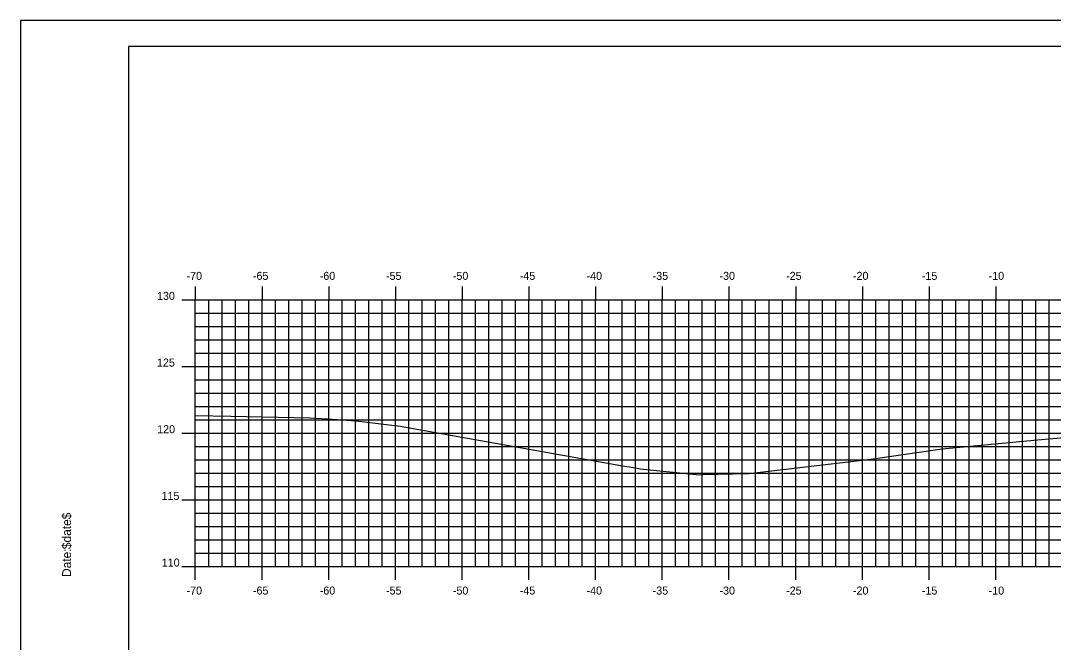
# Model space of a CAD drawing. Extents: x 852847 to 853019, y 365624 to 365734.
# Drawn here: x 852847.2 to 852924.6, y 365687.3 to 365734 of the extents above; entities that cross this region are included whole.
import ezdxf

# ---------------------------------------------------------------- set-up
doc = ezdxf.new("R2010")
doc.units = 0
for name, color, linetype in [('BORDER', 7, 'Continuous'), ('H_V ANNOTATION', 7, 'Continuous'), ('MAJOR', 7, 'Continuous'), ('MINOR', 7, 'Continuous'), ('PLOT BOUNDARY', 7, 'Continuous'), ('S_Roadway_Centerline', 7, 'Continuous')]:
    doc.layers.add(name, color=color, linetype=linetype)

msp = doc.modelspace()

# ---------------------------------------------------------------- linework, layer by layer
at = {"layer": 'BORDER'}
msp.add_lwpolyline([(852855.305, 365627.027), (853015.305, 365627.027), (853015.305, 365732.027), (852855.305, 365732.027)], close=True, dxfattribs=at)
at = {"layer": 'MAJOR'}
for p, q in [((852860.305, 365714.029), (852860.305, 365713.027)), ((852865.305, 365714.029), (852865.305, 365713.027)), ((852870.305, 365714.029), (852870.305, 365713.027)), ((852875.305, 365714.029), (852875.305, 365713.027)), ((852880.305, 365714.029), (852880.305, 365713.027)), ((852885.305, 365714.029), (852885.305, 365713.027)), ((852890.305, 365714.029), (852890.305, 365713.027)), ((852895.305, 365714.029), (852895.305, 365713.027)), ((852900.305, 365714.029), (852900.305, 365713.027)), ((852905.305, 365714.029), (852905.305, 365713.027)), ((852910.305, 365714.029), (852910.305, 365713.027)), ((852915.305, 365714.029), (852915.305, 365713.027)), ((852920.305, 365714.029), (852920.305, 365713.027)), ((852859.303, 365713.027), (852860.305, 365713.027)), ((852860.305, 365713.027), (853000.305, 365713.027)), ((852860.305, 365693.027), (852860.305, 365713.027)), ((852860.305, 365693.027), (852860.305, 365713.027)), ((852860.305, 365713.027), (853000.305, 365713.027)), ((852865.305, 365693.027), (852865.305, 365713.027)), ((852870.305, 365693.027), (852870.305, 365713.027)), ((852875.305, 365693.027), (852875.305, 365713.027)), ((852880.305, 365693.027), (852880.305, 365713.027)), ((852885.305, 365693.027), (852885.305, 365713.027)), ((852890.305, 365693.027), (852890.305, 365713.027)), ((852895.305, 365693.027), (852895.305, 365713.027)), ((852900.305, 365693.027), (852900.305, 365713.027)), ((852905.305, 365693.027), (852905.305, 365713.027)), ((852910.305, 365693.027), (852910.305, 365713.027)), ((852915.305, 365693.027), (852915.305, 365713.027)), ((852920.305, 365693.027), (852920.305, 365713.027)), ((852859.303, 365708.027), (852860.305, 365708.027)), ((852860.305, 365708.027), (853000.305, 365708.027)), ((852859.303, 365703.027), (852860.305, 365703.027)), ((852860.305, 365703.027), (853000.305, 365703.027)), ((852859.303, 365698.027), (852860.305, 365698.027)), ((852860.305, 365698.027), (853000.305, 365698.027)), ((852859.303, 365693.027), (852860.305, 365693.027)), ((852860.305, 365693.027), (853000.305, 365693.027)), ((852860.305, 365693.027), (853000.305, 365693.027)), ((852860.305, 365692.025), (852860.305, 365693.027)), ((852865.305, 365692.025), (852865.305, 365693.027)), ((852870.305, 365692.025), (852870.305, 365693.027)), ((852875.305, 365692.025), (852875.305, 365693.027)), ((852880.305, 365692.025), (852880.305, 365693.027)), ((852885.305, 365692.025), (852885.305, 365693.027)), ((852890.305, 365692.025), (852890.305, 365693.027)), ((852895.305, 365692.025), (852895.305, 365693.027)), ((852900.305, 365692.025), (852900.305, 365693.027)), ((852905.305, 365692.025), (852905.305, 365693.027)), ((852910.305, 365692.025), (852910.305, 365693.027)), ((852915.305, 365692.025), (852915.305, 365693.027)), ((852920.305, 365692.025), (852920.305, 365693.027))]:
    msp.add_line(p, q, dxfattribs=at)
at = {"layer": 'MINOR'}
for p, q in [((852861.305, 365693.027), (852861.305, 365713.027)), ((852862.305, 365693.027), (852862.305, 365713.027)), ((852863.305, 365693.027), (852863.305, 365713.027)), ((852864.305, 365693.027), (852864.305, 365713.027)), ((852866.305, 365693.027), (852866.305, 365713.027)), ((852867.305, 365693.027), (852867.305, 365713.027)), ((852868.305, 365693.027), (852868.305, 365713.027)), ((852869.305, 365693.027), (852869.305, 365713.027)), ((852871.305, 365693.027), (852871.305, 365713.027)), ((852872.305, 365693.027), (852872.305, 365713.027)), ((852873.305, 365693.027), (852873.305, 365713.027)), ((852874.305, 365693.027), (852874.305, 365713.027)), ((852876.305, 365693.027), (852876.305, 365713.027)), ((852877.305, 365693.027), (852877.305, 365713.027)), ((852878.305, 365693.027), (852878.305, 365713.027)), ((852879.305, 365693.027), (852879.305, 365713.027)), ((852881.305, 365693.027), (852881.305, 365713.027)), ((852882.305, 365693.027), (852882.305, 365713.027)), ((852883.305, 365693.027), (852883.305, 365713.027)), ((852884.305, 365693.027), (852884.305, 365713.027)), ((852886.305, 365693.027), (852886.305, 365713.027)), ((852887.305, 365693.027), (852887.305, 365713.027)), ((852888.305, 365693.027), (852888.305, 365713.027)), ((852889.305, 365693.027), (852889.305, 365713.027)), ((852891.305, 365693.027), (852891.305, 365713.027)), ((852892.305, 365693.027), (852892.305, 365713.027)), ((852893.305, 365693.027), (852893.305, 365713.027)), ((852894.305, 365693.027), (852894.305, 365713.027)), ((852896.305, 365693.027), (852896.305, 365713.027)), ((852897.305, 365693.027), (852897.305, 365713.027)), ((852898.305, 365693.027), (852898.305, 365713.027)), ((852899.305, 365693.027), (852899.305, 365713.027)), ((852901.305, 365693.027), (852901.305, 365713.027)), ((852902.305, 365693.027), (852902.305, 365713.027)), ((852903.305, 365693.027), (852903.305, 365713.027)), ((852904.305, 365693.027), (852904.305, 365713.027)), ((852906.305, 365693.027), (852906.305, 365713.027)), ((852907.305, 365693.027), (852907.305, 365713.027)), ((852908.305, 365693.027), (852908.305, 365713.027)), ((852909.305, 365693.027), (852909.305, 365713.027)), ((852911.305, 365693.027), (852911.305, 365713.027)), ((852912.305, 365693.027), (852912.305, 365713.027)), ((852913.305, 365693.027), (852913.305, 365713.027)), ((852914.305, 365693.027), (852914.305, 365713.027)), ((852916.305, 365693.027), (852916.305, 365713.027)), ((852917.305, 365693.027), (852917.305, 365713.027)), ((852918.305, 365693.027), (852918.305, 365713.027)), ((852919.305, 365693.027), (852919.305, 365713.027)), ((852921.305, 365693.027), (852921.305, 365713.027)), ((852922.305, 365693.027), (852922.305, 365713.027)), ((852923.305, 365693.027), (852923.305, 365713.027)), ((852924.305, 365693.027), (852924.305, 365713.027)), ((852860.305, 365712.027), (853000.305, 365712.027)), ((852860.305, 365712.027), (852861.307, 365712.027)), ((852860.305, 365711.027), (853000.305, 365711.027)), ((852860.305, 365711.027), (852861.307, 365711.027)), ((852860.305, 365710.027), (853000.305, 365710.027)), ((852860.305, 365710.027), (852861.307, 365710.027)), ((852860.305, 365709.027), (853000.305, 365709.027)), ((852860.305, 365709.027), (852861.307, 365709.027)), ((852860.305, 365707.027), (853000.305, 365707.027)), ((852860.305, 365707.027), (852861.307, 365707.027)), ((852860.305, 365706.027), (853000.305, 365706.027)), ((852860.305, 365706.027), (852861.307, 365706.027)), ((852860.305, 365705.027), (853000.305, 365705.027)), ((852860.305, 365705.027), (852861.307, 365705.027)), ((852860.305, 365704.027), (853000.305, 365704.027)), ((852860.305, 365704.027), (852861.307, 365704.027)), ((852860.305, 365702.027), (853000.305, 365702.027)), ((852860.305, 365702.027), (852861.307, 365702.027)), ((852860.305, 365701.027), (853000.305, 365701.027)), ((852860.305, 365701.027), (852861.307, 365701.027)), ((852860.305, 365700.027), (853000.305, 365700.027)), ((852860.305, 365700.027), (852861.307, 365700.027)), ((852860.305, 365699.027), (853000.305, 365699.027)), ((852860.305, 365699.027), (852861.307, 365699.027)), ((852860.305, 365697.027), (853000.305, 365697.027)), ((852860.305, 365697.027), (852861.307, 365697.027)), ((852860.305, 365696.027), (853000.305, 365696.027)), ((852860.305, 365696.027), (852861.307, 365696.027)), ((852860.305, 365695.027), (853000.305, 365695.027)), ((852860.305, 365695.027), (852861.307, 365695.027)), ((852860.305, 365694.027), (853000.305, 365694.027)), ((852860.305, 365694.027), (852861.307, 365694.027))]:
    msp.add_line(p, q, dxfattribs=at)
at = {"layer": 'PLOT BOUNDARY'}
msp.add_lwpolyline([(852847.212, 365623.968), (853017.212, 365623.968), (853017.212, 365733.968), (852847.212, 365733.968)], close=True, dxfattribs=at)
at = {"layer": 'S_Roadway_Centerline'}
msp.add_lwpolyline([(852860.305, 365704.347), (852862.962, 365704.305), (852868.895, 365704.17), (852870.201, 365704.112), (852872.361, 365703.964), (852875.656, 365703.564), (852892.471, 365700.548), (852893.324, 365700.419), (852893.652, 365700.354), (852898.103, 365699.911), (852898.302, 365699.931), (852901.805, 365699.993), (852910.949, 365701.08), (852916.286, 365701.847), (852923.423, 365702.524), (852930.953, 365703.18)], dxfattribs=at)

# ---------------------------------------------------------------- texts
at = {"layer": 'BORDER'}
for s, p in [('$date$', (852850.99, 365694.332)), ('Date:', (852850.99, 365692.244))]:
    msp.add_text(s, height=0.6696, rotation=90, dxfattribs=at).set_placement(p)
at = {"layer": 'H_V ANNOTATION'}
for s, p in [('-70', (852859.647, 365714.527)), ('-65', (852864.623, 365714.527)), ('-60', (852869.631, 365714.527)), ('-55', (852874.601, 365714.527)), ('-50', (852879.609, 365714.527)), ('-45', (852884.623, 365714.527)), ('-40', (852889.631, 365714.527)), ('-35', (852894.585, 365714.527)), ('-30', (852899.593, 365714.527)), ('-25', (852904.59, 365714.527)), ('-20', (852909.598, 365714.527)), ('-15', (852914.762, 365714.527)), ('-10', (852919.77, 365714.527)), ('130', (852857.435, 365713.027)), ('125', (852857.429, 365708.027)), ('120', (852857.445, 365703.027)), ('115', (852857.772, 365698.027)), ('110', (852857.788, 365693.027)), ('-70', (852859.647, 365690.927)), ('-65', (852864.623, 365690.927)), ('-60', (852869.631, 365690.927)), ('-55', (852874.601, 365690.927)), ('-50', (852879.609, 365690.927)), ('-45', (852884.623, 365690.927)), ('-40', (852889.631, 365690.927)), ('-35', (852894.585, 365690.927)), ('-30', (852899.593, 365690.927)), ('-25', (852904.59, 365690.927)), ('-20', (852909.598, 365690.927)), ('-15', (852914.762, 365690.927)), ('-10', (852919.77, 365690.927))]:
    msp.add_text(s, height=0.6, dxfattribs=at).set_placement(p)
at = {"layer": 'MAJOR'}
msp.add_text('-', height=0.006, dxfattribs=at).set_placement((852860.3, 365693.027))

doc.saveas('drawing.dxf')
